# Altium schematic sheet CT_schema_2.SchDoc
size 398 x 262 mm
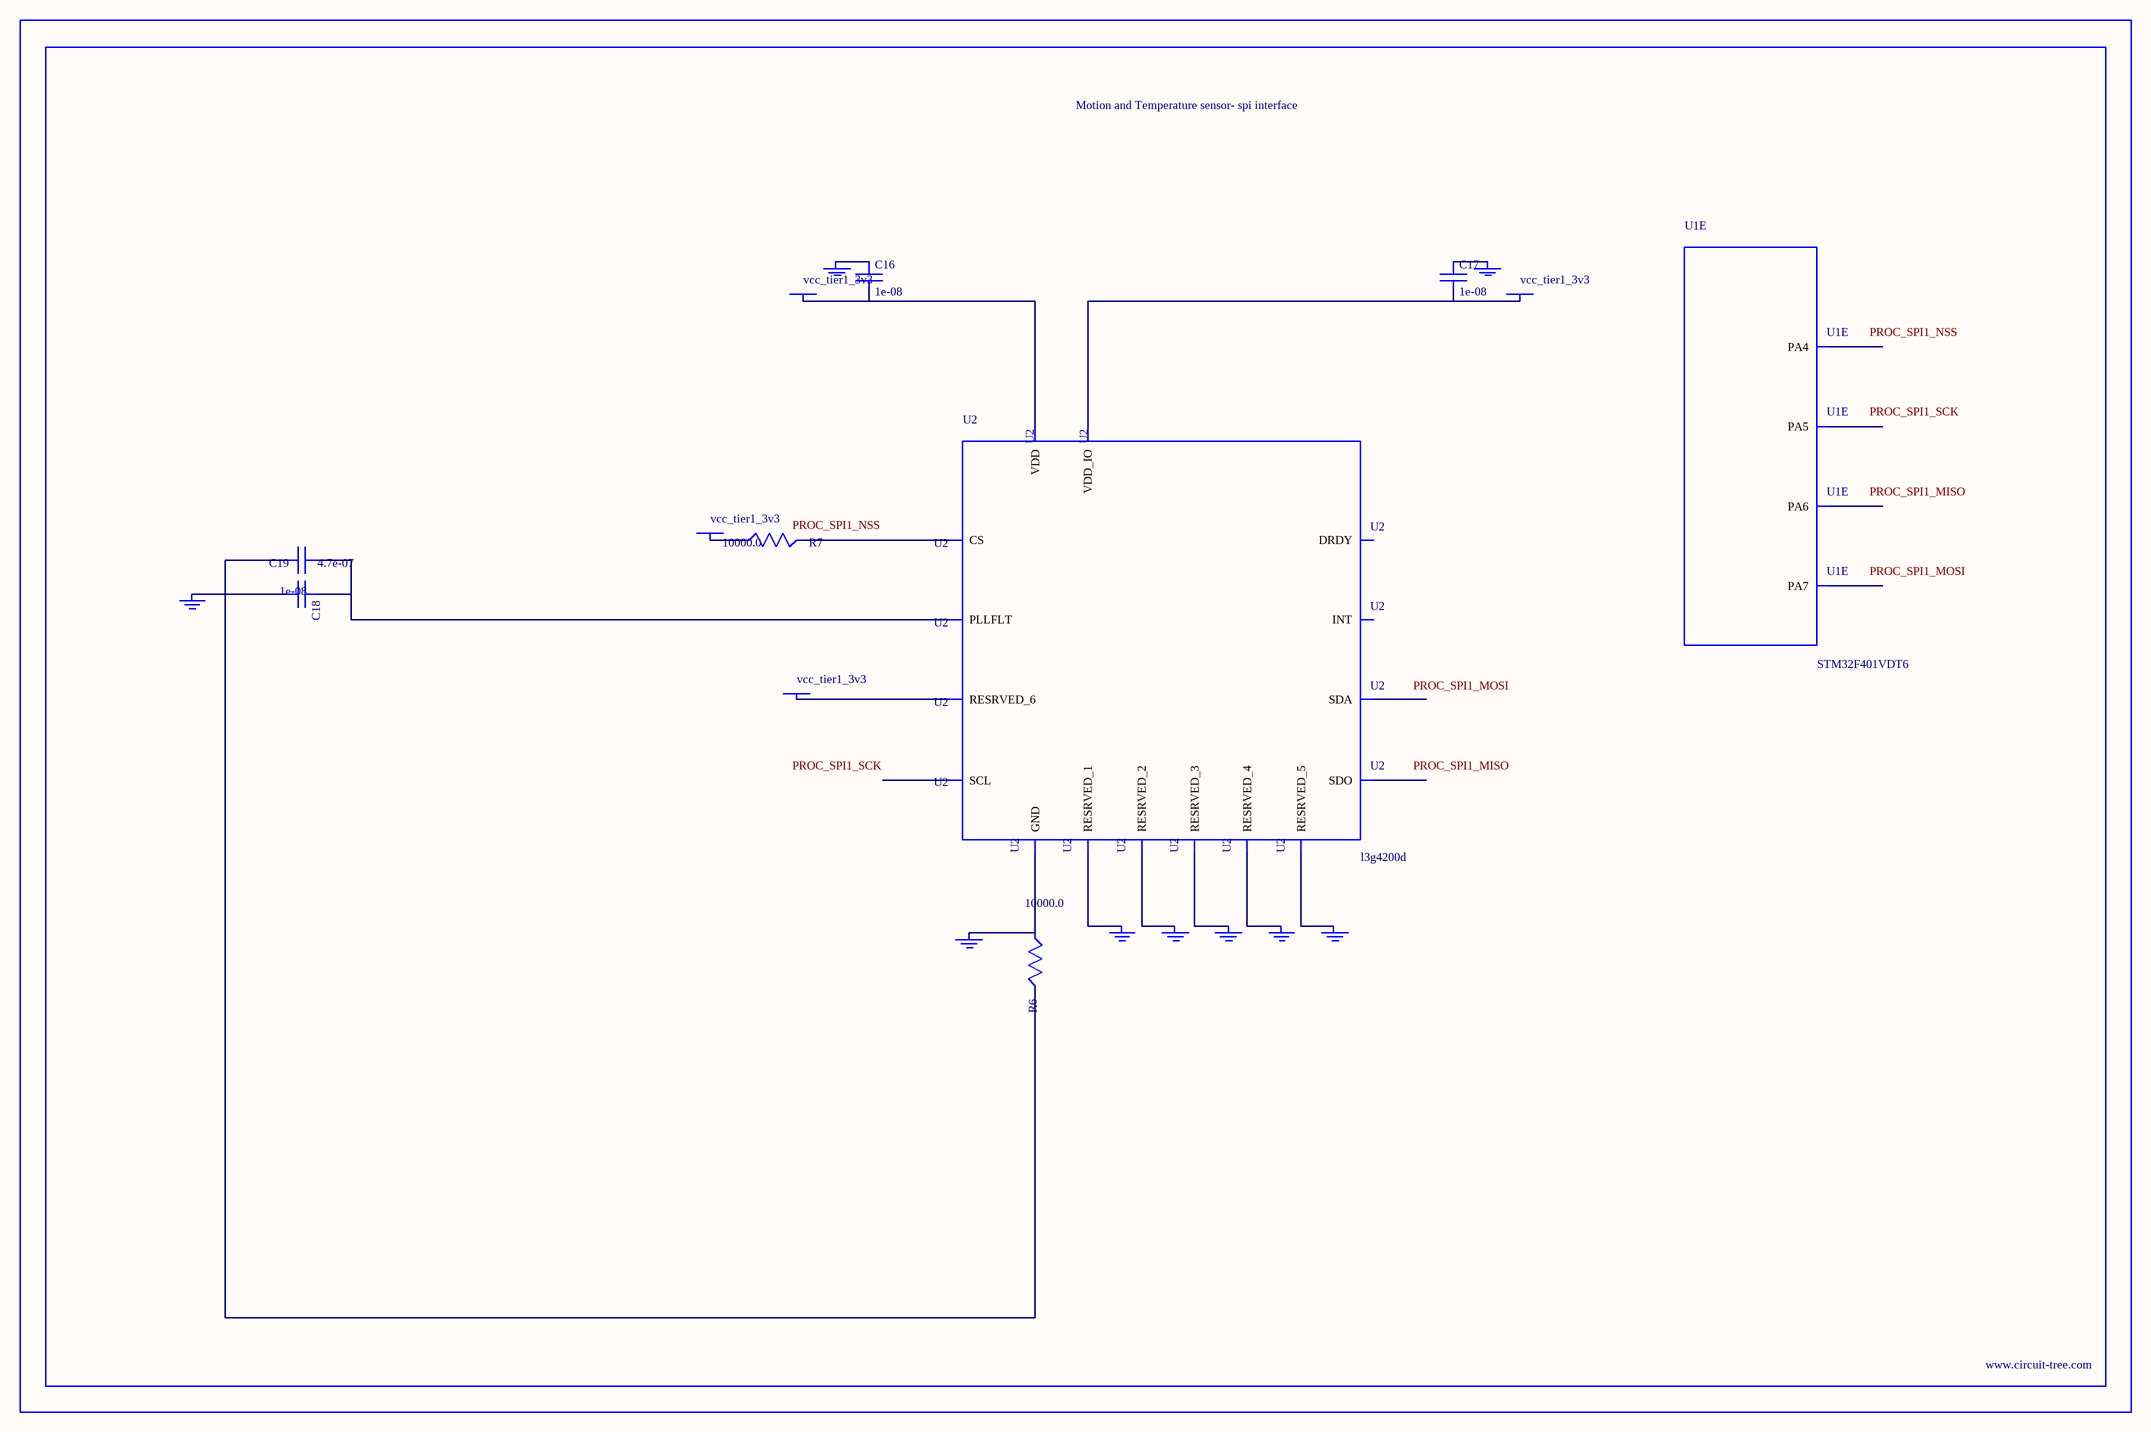
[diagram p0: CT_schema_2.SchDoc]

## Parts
BORDER1  (no value)
C16  1e-08  [C0402]
C17  1e-08  [C0402]
C18  1e-08  [C0402]
C19  4.7e-07  [C0603]
GND_INSTANCE_1_0  (no value)
GND_INSTANCE_1_1  (no value)
GND_INSTANCE_1_2  (no value)
GND_INSTANCE_1_3  (no value)
GND_INSTANCE_1_4  (no value)
GND_INSTANCE_1_5  (no value)
GND_INSTANCE_1_6  (no value)
GND_INSTANCE_1_7  (no value)
GND_INSTANCE_1_8  (no value)
POWER_INSTANCE_1_0  vcc_tier1_3v3
POWER_INSTANCE_1_1  vcc_tier1_3v3
POWER_INSTANCE_1_2  vcc_tier1_3v3
POWER_INSTANCE_1_3  vcc_tier1_3v3
R6  10000.0  [R0603]
R7  10000.0  [R0603]
U1  STM32F401VDT6  [LQFP100]  (part E of 10)
U2  l3g4200d  [LGA-16]

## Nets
NetC16_1: C16.1 GND_INSTANCE_1_8.0(GND)
NetC16_2: C16.2 POWER_INSTANCE_1_3.0(PWR) U2.16(VDD)
NetC17_1: C17.1 GND_INSTANCE_1_0.0(GND)
NetC17_2: C17.2 POWER_INSTANCE_1_0.0(PWR) U2.1(VDD_IO)
NetC18_1: C18.1 C19.1 U2.14(PLLFLT)
NetC18_2: C18.2 C19.2 GND_INSTANCE_1_7.0(GND) R6.2
NetGND_INSTANCE_1_1_0: GND_INSTANCE_1_1.0(GND) U2.8(RESRVED_1)
NetGND_INSTANCE_1_2_0: GND_INSTANCE_1_2.0(GND) U2.9(RESRVED_2)
NetGND_INSTANCE_1_3_0: GND_INSTANCE_1_3.0(GND) U2.10(RESRVED_3)
NetGND_INSTANCE_1_4_0: GND_INSTANCE_1_4.0(GND) U2.11(RESRVED_4)
NetGND_INSTANCE_1_5_0: GND_INSTANCE_1_5.0(GND) U2.12(RESRVED_5)
NetGND_INSTANCE_1_6_0: GND_INSTANCE_1_6.0(GND) R6.1 U2.13(GND)
NetPOWER_INSTANCE_1_1_0: POWER_INSTANCE_1_1.0(PWR) R7.1
NetPOWER_INSTANCE_1_2_0: POWER_INSTANCE_1_2.0(PWR) U2.15(RESRVED_6)
NetR7_2: R7.2 U2.5(CS)

Not connected (* = marked no-connect by the designer): U1 29(PA4) 30(PA5) 31(PA6) 32(PA7); U2 2(SCL) 3(SDA) 4(SDO) 6(DRDY) 7(INT)

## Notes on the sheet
- Labels drawn without touching a wire or pin: PROC_SPI1_MISO, PROC_SPI1_MOSI, PROC_SPI1_NSS, PROC_SPI1_SCK

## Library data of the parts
BORDER1 = BORDER_PAGE1
C16-C18 = C0402C103K3RAC
C19 = C0603C474K3RAC
GND_INSTANCE_1_0-GND_INSTANCE_1_8 = GND
POWER_INSTANCE_1_0-POWER_INSTANCE_1_3 = PWR
R6 R7 = RC0603JR-0710KL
